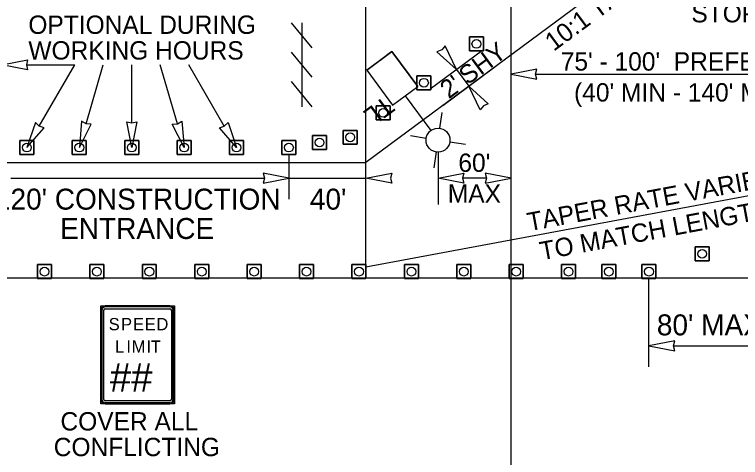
# Model space of a CAD drawing. Extents: x 99979.8 to 100075.7, y 99995 to 100010.7.
# Drawn here: x 100022.228 to 100024.999, y 100005.493 to 100007.184 of the extents above; entities that cross this region are included whole.
import ezdxf

# ---------------------------------------------------------------- set-up
doc = ezdxf.new("R2010")
doc.units = 0
for name, color, linetype in [('RD_ED_ShoulderPavedEdge', 7, 'Continuous'), ('RD_MK_LineEdgeWhite', 7, 'Continuous'), ('TR_SN_ConstructionSigns', 7, 'Continuous'), ('TR_WZ_BarricadeType3', 7, 'Continuous'), ('TR_WZ_PortableLightStandard', 7, 'Continuous'), ('TR_WZ_TrafficCone', 7, 'Continuous'), ('TR_WZ_WorkZoneDetails', 7, 'Continuous'), ('TR_WZ_WorkZoneTextCurrent', 7, 'Continuous')]:
    doc.layers.add(name, color=color, linetype=linetype)

msp = doc.modelspace()

# ---------------------------------------------------------------- linework, layer by layer
at = {"layer": 'RD_ED_ShoulderPavedEdge'}
msp.add_line((100020.3, 100006.1793), (100035.6425, 100006.1793), dxfattribs=at)
at = {"layer": 'RD_MK_LineEdgeWhite'}
for p, q in [((100024.8112, 100007.5393), (100023.5692, 100006.6193)), ((100020.3, 100006.6193), (100023.5692, 100006.6193)), ((100025.5008, 100006.5793), (100023.5692, 100006.2193))]:
    msp.add_line(p, q, dxfattribs=at)
at = {"layer": 'TR_SN_ConstructionSigns'}
for p, q in [((100022.5571, 100005.715), (100022.5571, 100006.0549)), ((100022.5571, 100006.0549), (100022.5571, 100005.715)), ((100022.562, 100006.0549), (100022.562, 100005.715)), ((100022.5689, 100005.715), (100022.5689, 100006.0549)), ((100022.5747, 100006.0725), (100022.8208, 100006.0725)), ((100022.8208, 100006.0725), (100022.5747, 100006.0725)), ((100022.8208, 100006.0676), (100022.5747, 100006.0676)), ((100022.5747, 100006.0607), (100022.8208, 100006.0607)), ((100022.8267, 100006.0549), (100022.8267, 100005.715)), ((100022.8335, 100005.715), (100022.8335, 100006.0549)), ((100022.8384, 100006.0549), (100022.8384, 100005.715)), ((100022.8384, 100005.715), (100022.8384, 100006.0549)), ((100022.8208, 100005.7092), (100022.5747, 100005.7092)), ((100022.5747, 100005.7024), (100022.8208, 100005.7024)), ((100022.8208, 100005.6975), (100022.5747, 100005.6975)), ((100022.5747, 100005.6975), (100022.8208, 100005.6975))]:
    msp.add_line(p, q, dxfattribs=at)
msp.add_lwpolyline([(100022.5571, 100006.0725), (100022.8384, 100006.0725), (100022.8384, 100005.6975), (100022.5571, 100005.6975)], close=True, dxfattribs=at)
for centre, radius, start, end in [((100022.5747, 100006.0549), 0.0176, 90, 180), ((100022.5747, 100006.0549), 0.0176, 90, 180), ((100022.5747, 100006.0549), 0.0127, 90, 180), ((100022.5747, 100006.0549), 0.00586, 90, 180), ((100022.8208, 100006.0549), 0.0176, 0, 90), ((100022.8208, 100006.0549), 0.0176, 0, 90), ((100022.8208, 100006.0549), 0.0127, 0, 90), ((100022.8208, 100006.0549), 0.00586, 360, 90), ((100022.5747, 100005.715), 0.0176, 180, 270), ((100022.5747, 100005.715), 0.0176, 180, 270), ((100022.5747, 100005.715), 0.0127, 180, 270), ((100022.5747, 100005.715), 0.00586, 180, 270), ((100022.8208, 100005.715), 0.0176, 270, 0), ((100022.8208, 100005.715), 0.0127, 270, 360), ((100022.8208, 100005.715), 0.00586, 270, 0), ((100022.8208, 100005.715), 0.0176, 270, 0)]:
    msp.add_arc(centre, radius, start, end, dxfattribs=at)
at = {"layer": 'TR_WZ_BarricadeType3'}
for p, q in [((100023.3645, 100007.0567), (100023.2852, 100007.1522)), ((100023.3248, 100007.1522), (100023.3248, 100006.8322)), ((100023.3645, 100006.9445), (100023.2852, 100007.04)), ((100023.3645, 100006.8322), (100023.2852, 100006.9278))]:
    msp.add_line(p, q, dxfattribs=at)
at = {"layer": 'TR_WZ_PortableLightStandard'}
for p, q in [((100023.5722, 100006.9712), (100023.6686, 100007.0426)), ((100023.6686, 100007.0426), (100023.7674, 100006.9093)), ((100023.7674, 100006.9093), (100023.6686, 100007.0426)), ((100023.5722, 100006.9712), (100023.671, 100006.8379)), ((100023.5722, 100006.9712), (100023.671, 100006.8379)), ((100023.671, 100006.8379), (100023.7674, 100006.9093)), ((100023.7192, 100006.8736), (100023.817, 100006.7415)), ((100023.8511, 100006.75), (100023.8601, 100006.8102)), ((100023.799, 100006.7114), (100023.7389, 100006.7204)), ((100023.8896, 100006.698), (100023.9498, 100006.689)), ((100023.8375, 100006.6594), (100023.8286, 100006.5992))]:
    msp.add_line(p, q, dxfattribs=at)
for points in [[(100023.6686, 100007.0426), (100023.6204, 100007.0069), (100023.5722, 100006.9712)], [(100023.671, 100006.8379), (100023.7192, 100006.8736), (100023.7674, 100006.9093)]]:
    msp.add_lwpolyline(points, dxfattribs=at)
msp.add_circle((100023.8443, 100006.7047), 0.0457, dxfattribs=at)
msp.add_circle((100023.8443, 100006.7047), 0.0457, dxfattribs=at)
at = {"layer": 'TR_WZ_TrafficCone'}
for points in [[(100024.0174, 100007.0451), (100023.9641, 100007.0451), (100023.9641, 100007.0984), (100024.0174, 100007.0984), (100024.0174, 100007.0451)], [(100024.0174, 100007.0984), (100023.9641, 100007.0984), (100023.9641, 100007.0451), (100024.0174, 100007.0451), (100024.0174, 100007.0984)], [(100023.8174, 100006.8969), (100023.7641, 100006.8969), (100023.7641, 100006.9503), (100023.8174, 100006.9503), (100023.8174, 100006.8969)], [(100023.8174, 100006.9503), (100023.7641, 100006.9503), (100023.7641, 100006.8969), (100023.8174, 100006.8969), (100023.8174, 100006.9503)], [(100023.662, 100006.7818), (100023.6087, 100006.7818), (100023.6087, 100006.8352), (100023.662, 100006.8352), (100023.662, 100006.7818)], [(100023.662, 100006.8352), (100023.6087, 100006.8352), (100023.6087, 100006.7818), (100023.662, 100006.7818), (100023.662, 100006.8352)], [(100023.4192, 100006.669), (100023.3658, 100006.669), (100023.3658, 100006.7223), (100023.4192, 100006.7223), (100023.4192, 100006.669)], [(100023.4192, 100006.7223), (100023.3658, 100006.7223), (100023.3658, 100006.669), (100023.4192, 100006.669), (100023.4192, 100006.7223)], [(100023.4828, 100006.7419), (100023.5362, 100006.7419), (100023.5362, 100006.6886), (100023.4828, 100006.6886), (100023.4828, 100006.7419)], [(100023.4828, 100006.6886), (100023.5362, 100006.6886), (100023.5362, 100006.7419), (100023.4828, 100006.7419), (100023.4828, 100006.6886)], [(100022.3022, 100006.7026), (100022.2488, 100006.7026), (100022.2488, 100006.6493), (100022.3022, 100006.6493), (100022.3022, 100006.7026)], [(100022.3022, 100006.6493), (100022.2488, 100006.6493), (100022.2488, 100006.7026), (100022.3022, 100006.7026), (100022.3022, 100006.6493)], [(100022.5022, 100006.7026), (100022.4488, 100006.7026), (100022.4488, 100006.6493), (100022.5022, 100006.6493), (100022.5022, 100006.7026)], [(100022.5022, 100006.6493), (100022.4488, 100006.6493), (100022.4488, 100006.7026), (100022.5022, 100006.7026), (100022.5022, 100006.6493)], [(100022.7022, 100006.7026), (100022.6488, 100006.7026), (100022.6488, 100006.6493), (100022.7022, 100006.6493), (100022.7022, 100006.7026)], [(100022.7022, 100006.6493), (100022.6488, 100006.6493), (100022.6488, 100006.7026), (100022.7022, 100006.7026), (100022.7022, 100006.6493)], [(100022.9022, 100006.7026), (100022.8488, 100006.7026), (100022.8488, 100006.6493), (100022.9022, 100006.6493), (100022.9022, 100006.7026)], [(100022.9022, 100006.6493), (100022.8488, 100006.6493), (100022.8488, 100006.7026), (100022.9022, 100006.7026), (100022.9022, 100006.6493)], [(100023.1022, 100006.7026), (100023.0488, 100006.7026), (100023.0488, 100006.6493), (100023.1022, 100006.6493), (100023.1022, 100006.7026)], [(100023.1022, 100006.6493), (100023.0488, 100006.6493), (100023.0488, 100006.7026), (100023.1022, 100006.7026), (100023.1022, 100006.6493)], [(100023.3022, 100006.6493), (100023.2488, 100006.6493), (100023.2488, 100006.7026), (100023.3022, 100006.7026), (100023.3022, 100006.6493)], [(100023.3022, 100006.7026), (100023.2488, 100006.7026), (100023.2488, 100006.6493), (100023.3022, 100006.6493), (100023.3022, 100006.7026)], [(100024.8789, 100006.2439), (100024.8256, 100006.2439), (100024.8256, 100006.2973), (100024.8789, 100006.2973), (100024.8789, 100006.2439)], [(100024.8789, 100006.2973), (100024.8256, 100006.2973), (100024.8256, 100006.2439), (100024.8789, 100006.2439), (100024.8789, 100006.2973)], [(100022.316, 100006.2293), (100022.3693, 100006.2293), (100022.3693, 100006.176), (100022.316, 100006.176), (100022.316, 100006.2293)], [(100022.316, 100006.176), (100022.3693, 100006.176), (100022.3693, 100006.2293), (100022.316, 100006.2293), (100022.316, 100006.176)], [(100022.516, 100006.2293), (100022.5693, 100006.2293), (100022.5693, 100006.176), (100022.516, 100006.176), (100022.516, 100006.2293)], [(100022.516, 100006.176), (100022.5693, 100006.176), (100022.5693, 100006.2293), (100022.516, 100006.2293), (100022.516, 100006.176)], [(100022.716, 100006.2293), (100022.7693, 100006.2293), (100022.7693, 100006.176), (100022.716, 100006.176), (100022.716, 100006.2293)], [(100022.716, 100006.176), (100022.7693, 100006.176), (100022.7693, 100006.2293), (100022.716, 100006.2293), (100022.716, 100006.176)], [(100022.916, 100006.2293), (100022.9693, 100006.2293), (100022.9693, 100006.176), (100022.916, 100006.176), (100022.916, 100006.2293)], [(100022.916, 100006.176), (100022.9693, 100006.176), (100022.9693, 100006.2293), (100022.916, 100006.2293), (100022.916, 100006.176)], [(100023.116, 100006.2293), (100023.1693, 100006.2293), (100023.1693, 100006.176), (100023.116, 100006.176), (100023.116, 100006.2293)], [(100023.116, 100006.176), (100023.1693, 100006.176), (100023.1693, 100006.2293), (100023.116, 100006.2293), (100023.116, 100006.176)], [(100023.316, 100006.2293), (100023.3693, 100006.2293), (100023.3693, 100006.176), (100023.316, 100006.176), (100023.316, 100006.2293)], [(100023.316, 100006.176), (100023.3693, 100006.176), (100023.3693, 100006.2293), (100023.316, 100006.2293), (100023.316, 100006.176)], [(100023.516, 100006.2293), (100023.5693, 100006.2293), (100023.5693, 100006.176), (100023.516, 100006.176), (100023.516, 100006.2293)], [(100023.516, 100006.176), (100023.5693, 100006.176), (100023.5693, 100006.2293), (100023.516, 100006.2293), (100023.516, 100006.176)], [(100023.716, 100006.2293), (100023.7693, 100006.2293), (100023.7693, 100006.176), (100023.716, 100006.176), (100023.716, 100006.2293)], [(100023.716, 100006.176), (100023.7693, 100006.176), (100023.7693, 100006.2293), (100023.716, 100006.2293), (100023.716, 100006.176)], [(100023.916, 100006.2293), (100023.9693, 100006.2293), (100023.9693, 100006.176), (100023.916, 100006.176), (100023.916, 100006.2293)], [(100023.916, 100006.176), (100023.9693, 100006.176), (100023.9693, 100006.2293), (100023.916, 100006.2293), (100023.916, 100006.176)], [(100024.116, 100006.2293), (100024.1693, 100006.2293), (100024.1693, 100006.176), (100024.116, 100006.176), (100024.116, 100006.2293)], [(100024.116, 100006.176), (100024.1693, 100006.176), (100024.1693, 100006.2293), (100024.116, 100006.2293), (100024.116, 100006.176)], [(100024.316, 100006.2293), (100024.3693, 100006.2293), (100024.3693, 100006.176), (100024.316, 100006.176), (100024.316, 100006.2293)], [(100024.316, 100006.176), (100024.3693, 100006.176), (100024.3693, 100006.2293), (100024.316, 100006.2293), (100024.316, 100006.176)], [(100024.4694, 100006.2293), (100024.5227, 100006.2293), (100024.5227, 100006.176), (100024.4694, 100006.176), (100024.4694, 100006.2293)], [(100024.4694, 100006.176), (100024.5227, 100006.176), (100024.5227, 100006.2293), (100024.4694, 100006.2293), (100024.4694, 100006.176)], [(100024.6761, 100006.176), (100024.6227, 100006.176), (100024.6227, 100006.2293), (100024.6761, 100006.2293), (100024.6761, 100006.176)], [(100024.6761, 100006.2293), (100024.6227, 100006.2293), (100024.6227, 100006.176), (100024.6761, 100006.176), (100024.6761, 100006.2293)]]:
    msp.add_lwpolyline(points, dxfattribs=at)
for centre in [(100023.9907, 100007.0718), (100023.7907, 100006.9236), (100023.6354, 100006.8085), (100023.5095, 100006.7153), (100022.2755, 100006.676), (100022.4755, 100006.676), (100022.6755, 100006.676), (100022.8755, 100006.676), (100023.0755, 100006.676), (100023.2755, 100006.676), (100023.3925, 100006.6956), (100024.8523, 100006.2706), (100022.3427, 100006.2026), (100022.5427, 100006.2026), (100022.7427, 100006.2026), (100022.9427, 100006.2026), (100023.1427, 100006.2026), (100023.3427, 100006.2026), (100023.5427, 100006.2026), (100023.7427, 100006.2026), (100023.9427, 100006.2026), (100024.1427, 100006.2026), (100024.3427, 100006.2026), (100024.496, 100006.2026), (100024.6494, 100006.2026)]:
    msp.add_circle(centre, 0.0167, dxfattribs=at)
at = {"layer": 'TR_WZ_WorkZoneDetails'}
for p, q in [((100023.5692, 100006.2193), (100023.5692, 100008.2793)), ((100024.1231, 100004.9817), (100024.1231, 100007.2294)), ((100023.8141, 100006.9003), (100024.0141, 100007.0484)), ((100022.2733, 100006.9922), (100022.4578, 100006.9922)), ((100022.3225, 100006.7578), (100022.4578, 100006.9922)), ((100022.5016, 100006.7667), (100022.5667, 100006.9922)), ((100022.6756, 100006.7703), (100022.6756, 100006.9922)), ((100022.8496, 100006.7667), (100022.7845, 100006.9922)), ((100023.0287, 100006.7578), (100022.8933, 100006.9922)), ((100023.8621, 100006.8363), (100024.0617, 100006.9841)), ((100024.2168, 100006.956), (100025.4071, 100006.956)), ((100023.2756, 100006.6493), (100023.2756, 100006.4793)), ((100023.8443, 100006.659), (100023.8443, 100006.4593)), ((100022.2137, 100006.5593), (100023.1819, 100006.5593)), ((100023.2756, 100006.5593), (100023.5692, 100006.5593)), ((100024.0294, 100006.5593), (100023.9381, 100006.5593)), ((100024.6494, 100005.8393), (100024.6494, 100006.1793)), ((100024.7431, 100005.9193), (100025.4071, 100005.9193))]:
    msp.add_line(p, q, dxfattribs=at)
for points in [[(100023.9143, 100006.9745), (100023.8713, 100007.0649), (100023.8585, 100007.0498), (100023.8403, 100007.042)], [(100022.1796, 100006.9922), (100022.2779, 100007.0115), (100022.2733, 100006.9922), (100022.2778, 100006.9729)], [(100024.1231, 100006.956), (100024.2214, 100006.9367), (100024.2168, 100006.956), (100024.2214, 100006.9753)], [(100023.9619, 100006.9102), (100024.0359, 100006.8427), (100024.0177, 100006.8349), (100024.0049, 100006.8198)], [(100022.4756, 100006.6766), (100022.5213, 100006.7657), (100022.5015, 100006.7667), (100022.4843, 100006.7764)], [(100022.6756, 100006.6766), (100022.6564, 100006.7749), (100022.6756, 100006.7703), (100022.6949, 100006.7749)], [(100022.8756, 100006.6766), (100022.8299, 100006.7657), (100022.8496, 100006.7667), (100022.8669, 100006.7764)], [(100022.2756, 100006.6766), (100022.3414, 100006.7521), (100022.3224, 100006.7578), (100022.308, 100006.7714)], [(100023.0756, 100006.6766), (100023.0098, 100006.7521), (100023.0288, 100006.7578), (100023.0432, 100006.7714)], [(100023.2756, 100006.5593), (100023.1773, 100006.5786), (100023.1819, 100006.5593), (100023.1773, 100006.54)], [(100023.5692, 100006.5593), (100023.6675, 100006.5786), (100023.6629, 100006.5593), (100023.6675, 100006.54)], [(100023.8443, 100006.5593), (100023.9426, 100006.5786), (100023.9381, 100006.5593), (100023.9426, 100006.54)], [(100024.1231, 100006.5593), (100024.0248, 100006.5786), (100024.0294, 100006.5593), (100024.0248, 100006.54)], [(100024.6494, 100005.9193), (100024.7477, 100005.9), (100024.7431, 100005.9193), (100024.7477, 100005.9386)]]:
    msp.add_lwpolyline(points, close=True, dxfattribs=at)
msp.add_lwpolyline([(100023.9143, 100006.9745), (100023.9619, 100006.9102)], dxfattribs=at)

# ---------------------------------------------------------------- texts
at = {"layer": 'TR_SN_ConstructionSigns'}
for s, height, p in [('S', 0.0469, (100022.5876, 100005.9787)), ('P', 0.0469, (100022.6349, 100005.9787)), ('E', 0.0469, (100022.6809, 100005.9787)), ('E', 0.0469, (100022.7254, 100005.9787)), ('D', 0.0469, (100022.7699, 100005.9787)), ('L', 0.0469, (100022.612, 100005.8928)), ('I', 0.0469, (100022.6551, 100005.8928)), ('M', 0.0469, (100022.6757, 100005.8928)), ('I', 0.0469, (100022.732, 100005.8928)), ('T', 0.0469, (100022.7484, 100005.8928)), ('##', 0.10937, (100022.5917, 100005.7443)), ('COVER ALL', 0.07, (100022.4035, 100005.5962)), ('CONFLICTING', 0.07, (100022.3778, 100005.4982))]:
    msp.add_text(s, height=height, dxfattribs=at).set_placement(p)
at = {"layer": 'TR_WZ_PortableLightStandard'}
msp.add_text('TL', height=0.07, rotation=216.5289, dxfattribs=at).set_placement((100023.6425, 100006.8765))
at = {"layer": 'TR_WZ_WorkZoneTextCurrent'}
for s, rotation, p in [('10:1 TAPER', 36.5289, (100024.2858, 100007.0415)), ('SHY', 36.5289, (100023.9571, 100006.9129)), ("2' ", 36.5289, (100023.8854, 100006.8598)), ("60'", 360, (100023.922, 100006.5833)), ('TAPER RATE VARIES', 10.5573, (100024.1918, 100006.3568)), ('MAX', 360, (100023.8817, 100006.4653)), ('TO MATCH LENGTH', 10.5573, (100024.2395, 100006.2457))]:
    msp.add_text(s, height=0.07, rotation=rotation, dxfattribs=at).set_placement(p)
for s, height, p in [('STOP BAR', 0.07, (100024.8112, 100007.1541)), ('OPTIONAL DURING', 0.07, (100022.281, 100007.1102)), ('WORKING HOURS', 0.07, (100022.281, 100007.0122)), ("75' - 100'  PREFERRED", 0.07, (100024.3128, 100006.97)), ("(40' MIN - 140' MAX)", 0.07, (100024.3635, 100006.852)), ("120' CONSTRUCTION", 0.08, (100022.1533, 100006.4393)), ("40'", 0.08, (100023.3552, 100006.4393)), ('ENTRANCE', 0.08, (100022.402, 100006.3273)), ("80' MAX", 0.08, (100024.6794, 100005.9593))]:
    msp.add_text(s, height=height, dxfattribs=at).set_placement(p)

doc.saveas('drawing.dxf')
